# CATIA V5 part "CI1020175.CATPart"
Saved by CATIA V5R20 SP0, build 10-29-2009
Part number: CI1020175
Bounding box of the stored display mesh (mm): x -43.195 to 19, y -209.276 to 9, z -19 to 19
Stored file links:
  C:\Users\Raffaele\Desktop\3D X SITO CF\BOLEX\19-INCLINED ASSEMBLY REF_CI\CI1020175.CATPart
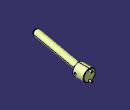
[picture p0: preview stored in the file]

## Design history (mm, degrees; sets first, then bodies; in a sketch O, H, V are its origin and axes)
Set1
  DatumSurface1 to DatumSurface23 "MANIFOLD_SOLID_BREP #695"
  DatumSurface24 to DatumSurface39 "MANIFOLD_SOLID_BREP #1118"
Body1 (main body)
